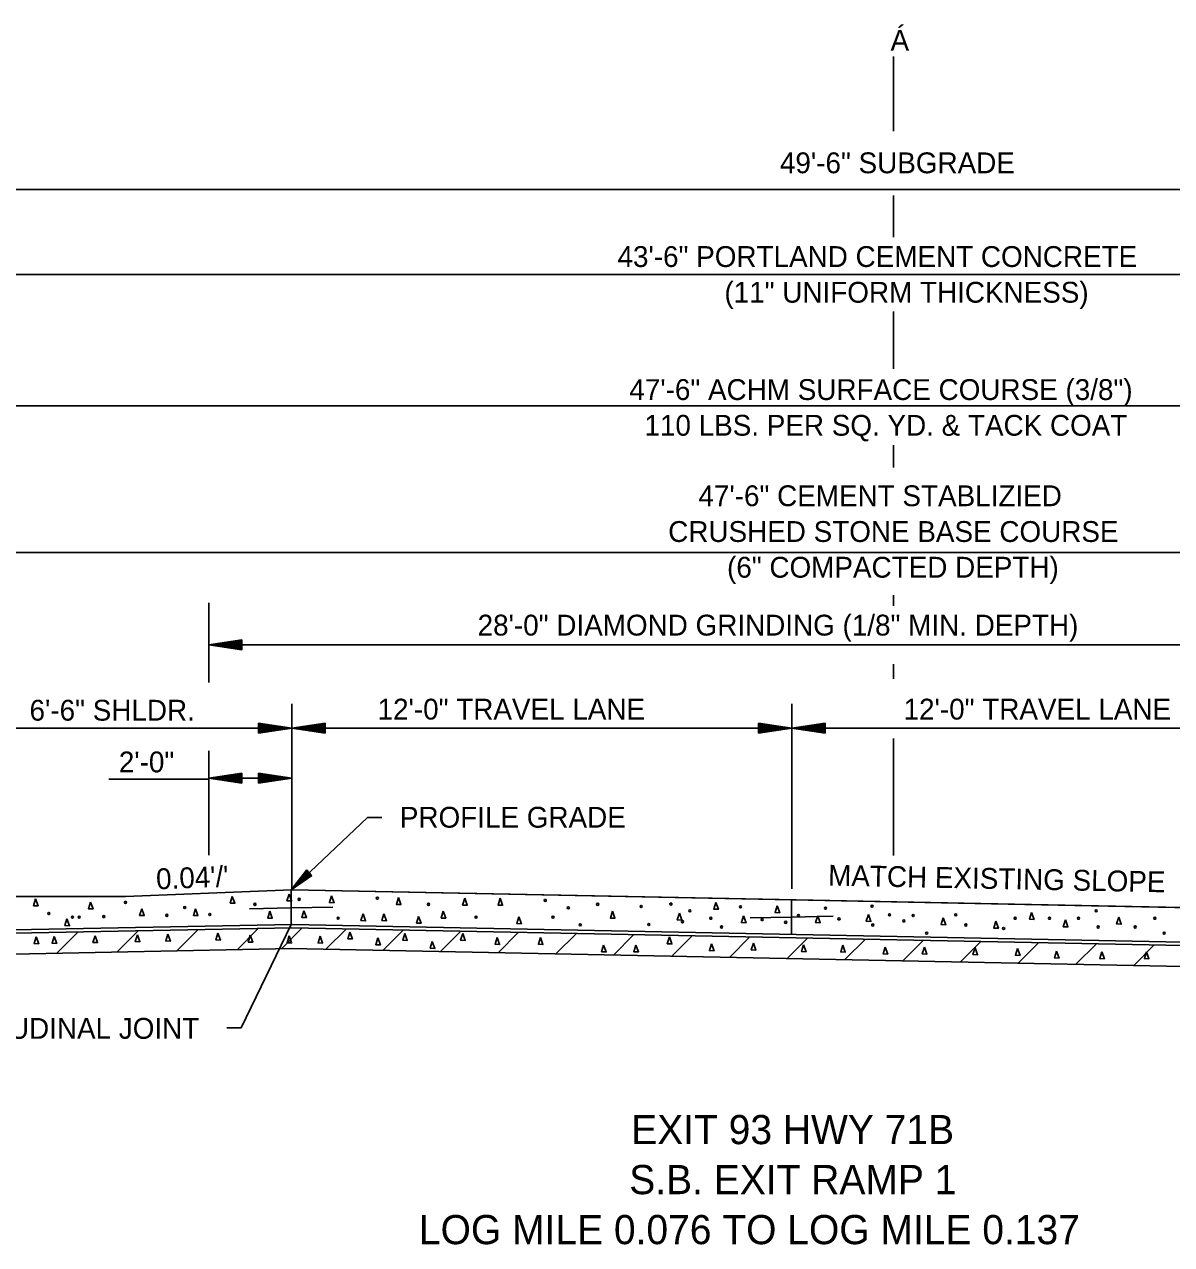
# Model space of a CAD drawing. Extents: x 60325 to 61047, y 53669 to 53767.
# Drawn here: x 60747.15 to 60774.69, y 53684.54 to 53713.82 of the extents above; entities that cross this region are included whole.
import ezdxf

# ---------------------------------------------------------------- set-up
doc = ezdxf.new("R2010")
doc.units = 0
doc.layers.add('R_Border', color=7, linetype='Continuous')
doc.layers.add('R_Border Prem', color=7, linetype='Continuous')

msp = doc.modelspace()

# ---------------------------------------------------------------- linework, layer by layer
at = {"layer": 'R_Border'}
for p, q in [((60751.572, 53698.024), (60751.572, 53699.939)), ((60752.372, 53699.046), (60751.572, 53698.926)), ((60752.372, 53699.026), (60751.706, 53698.926)), ((60752.372, 53698.806), (60752.372, 53699.046)), ((60752.372, 53698.806), (60751.572, 53698.926)), ((60779.572, 53698.926), (60751.572, 53698.926)), ((60752.372, 53698.826), (60751.706, 53698.926)), ((60752.372, 53699.005), (60751.843, 53698.926)), ((60752.372, 53698.846), (60751.843, 53698.926)), ((60752.372, 53698.985), (60751.977, 53698.926)), ((60752.372, 53698.866), (60751.977, 53698.926)), ((60752.372, 53698.965), (60752.112, 53698.926)), ((60752.372, 53698.887), (60752.112, 53698.926)), ((60752.372, 53698.945), (60752.246, 53698.926)), ((60752.372, 53698.907), (60752.246, 53698.926)), ((60753.57, 53693.371), (60753.57, 53697.513)), ((60754.37, 53697.052), (60753.57, 53696.932)), ((60754.37, 53697.032), (60753.704, 53696.932)), ((60754.37, 53697.011), (60753.841, 53696.932)), ((60754.37, 53696.991), (60753.975, 53696.932)), ((60754.37, 53696.971), (60754.11, 53696.932)), ((60754.37, 53696.812), (60754.37, 53697.052)), ((60764.77, 53697.052), (60765.57, 53696.932)), ((60764.77, 53697.052), (60764.77, 53696.812)), ((60764.77, 53697.032), (60765.437, 53696.932)), ((60764.77, 53697.011), (60765.299, 53696.932)), ((60764.77, 53696.991), (60765.166, 53696.932)), ((60764.77, 53696.971), (60765.03, 53696.932)), ((60766.37, 53697.052), (60765.57, 53696.932)), ((60766.37, 53697.032), (60765.704, 53696.932)), ((60766.37, 53697.011), (60765.841, 53696.932)), ((60766.37, 53696.991), (60765.975, 53696.932)), ((60766.37, 53696.971), (60766.11, 53696.932)), ((60766.37, 53696.812), (60766.37, 53697.052)), ((60777.57, 53696.932), (60753.57, 53696.932)), ((60754.37, 53696.812), (60753.57, 53696.932)), ((60754.37, 53696.832), (60753.704, 53696.932)), ((60754.37, 53696.852), (60753.841, 53696.932)), ((60754.37, 53696.872), (60753.975, 53696.932)), ((60754.37, 53696.893), (60754.11, 53696.932)), ((60754.37, 53696.951), (60754.244, 53696.932)), ((60754.37, 53696.913), (60754.244, 53696.932)), ((60764.77, 53696.951), (60764.897, 53696.932)), ((60764.77, 53696.812), (60765.57, 53696.932)), ((60764.77, 53696.893), (60765.03, 53696.932)), ((60764.77, 53696.852), (60765.299, 53696.932)), ((60764.77, 53696.832), (60765.437, 53696.932)), ((60764.77, 53696.872), (60765.166, 53696.932)), ((60764.77, 53696.913), (60764.897, 53696.932)), ((60766.37, 53696.812), (60765.57, 53696.932)), ((60766.37, 53696.832), (60765.704, 53696.932)), ((60766.37, 53696.852), (60765.841, 53696.932)), ((60766.37, 53696.872), (60765.975, 53696.932)), ((60766.37, 53696.893), (60766.11, 53696.932)), ((60766.37, 53696.951), (60766.244, 53696.932)), ((60766.37, 53696.913), (60766.244, 53696.932)), ((60751.572, 53693.881), (60751.572, 53696.382)), ((60752.372, 53695.847), (60751.572, 53695.727)), ((60752.372, 53695.827), (60751.706, 53695.727)), ((60752.372, 53695.806), (60751.843, 53695.727)), ((60752.372, 53695.847), (60752.372, 53695.607)), ((60752.772, 53695.847), (60753.572, 53695.727)), ((60752.772, 53695.847), (60752.772, 53695.607)), ((60752.772, 53695.827), (60753.439, 53695.727)), ((60752.772, 53695.806), (60753.301, 53695.727)), ((60751.572, 53695.707), (60749.178, 53695.707)), ((60753.572, 53695.727), (60751.572, 53695.727)), ((60752.372, 53695.607), (60751.572, 53695.727)), ((60752.372, 53695.627), (60751.706, 53695.727)), ((60752.372, 53695.647), (60751.843, 53695.727)), ((60752.372, 53695.786), (60751.977, 53695.727)), ((60752.372, 53695.667), (60751.977, 53695.727)), ((60752.372, 53695.765), (60752.112, 53695.727)), ((60752.372, 53695.687), (60752.112, 53695.727)), ((60752.372, 53695.745), (60752.246, 53695.727)), ((60752.372, 53695.708), (60752.246, 53695.727)), ((60752.772, 53695.786), (60753.168, 53695.727)), ((60752.772, 53695.765), (60753.032, 53695.727)), ((60752.772, 53695.745), (60752.899, 53695.727)), ((60752.772, 53695.607), (60753.572, 53695.727)), ((60752.772, 53695.687), (60753.032, 53695.727)), ((60752.772, 53695.647), (60753.301, 53695.727)), ((60752.772, 53695.627), (60753.439, 53695.727)), ((60752.772, 53695.667), (60753.168, 53695.727)), ((60752.772, 53695.708), (60752.899, 53695.727)), ((60753.554, 53693.033), (60753.554, 53692.2)), ((60753.554, 53692.617), (60752.555, 53692.597)), ((60754.554, 53692.637), (60753.554, 53692.617)), ((60765.568, 53692.812), (60765.568, 53691.979)), ((60765.568, 53692.395), (60764.568, 53692.375)), ((60766.568, 53692.415), (60765.568, 53692.395)), ((60752.353, 53689.741), (60753.554, 53692.221)), ((60752.007, 53689.741), (60752.353, 53689.741))]:
    msp.add_line(p, q, dxfattribs=at)
msp.add_lwpolyline([(60751.571, 53692.97), (60753.572, 53693.051), (60777.57, 53692.571), (60779.572, 53692.49)], dxfattribs=at)
at = {"layer": 'R_Border Prem'}
for p, q in [((60768.01, 53711.254), (60768.01, 53713.048)), ((60791.429, 53709.854), (60741.764, 53709.854)), ((60768.01, 53708.708), (60768.01, 53709.714)), ((60788.618, 53707.813), (60744.576, 53707.813)), ((60768.01, 53705.552), (60768.01, 53706.927)), ((60790.388, 53704.661), (60742.805, 53704.661)), ((60768.01, 53703.182), (60768.01, 53703.717)), ((60790.388, 53701.145), (60742.805, 53701.145)), ((60768.01, 53699.869), (60768.01, 53700.124)), ((60768.01, 53698.116), (60768.01, 53698.464)), ((60753.57, 53693.071), (60753.57, 53697.513)), ((60765.57, 53693.071), (60765.57, 53697.513)), ((60752.77, 53697.052), (60753.57, 53696.932)), ((60752.77, 53697.052), (60752.77, 53696.812)), ((60752.77, 53697.032), (60753.437, 53696.932)), ((60752.77, 53697.011), (60753.299, 53696.932)), ((60752.77, 53696.991), (60753.166, 53696.932)), ((60752.77, 53696.971), (60753.03, 53696.932)), ((60745.57, 53696.932), (60753.57, 53696.932)), ((60752.77, 53696.951), (60752.897, 53696.932)), ((60752.77, 53696.812), (60753.57, 53696.932)), ((60752.77, 53696.893), (60753.03, 53696.932)), ((60752.77, 53696.852), (60753.299, 53696.932)), ((60752.77, 53696.832), (60753.437, 53696.932)), ((60752.77, 53696.872), (60753.166, 53696.932)), ((60752.77, 53696.913), (60752.897, 53696.932)), ((60768.01, 53693.874), (60768.01, 53696.684)), ((60753.925, 53693.529), (60753.552, 53693.051)), ((60753.936, 53693.518), (60753.624, 53693.12)), ((60753.946, 53693.507), (60753.699, 53693.191)), ((60753.957, 53693.496), (60753.772, 53693.259)), ((60753.967, 53693.485), (60753.846, 53693.329)), ((60753.978, 53693.474), (60753.918, 53693.398)), ((60753.997, 53693.453), (60753.918, 53693.398)), ((60754.049, 53693.398), (60753.925, 53693.529)), ((60754.049, 53693.398), (60753.552, 53693.051)), ((60754.039, 53693.409), (60753.624, 53693.12)), ((60754.028, 53693.42), (60753.699, 53693.191)), ((60754.018, 53693.431), (60753.772, 53693.259)), ((60754.007, 53693.442), (60753.846, 53693.329)), ((60749.572, 53692.891), (60745.572, 53692.891)), ((60753.57, 53693.05), (60749.572, 53692.891)), ((60753.57, 53693.051), (60777.57, 53692.571)), ((60753.572, 53692.141), (60742.639, 53691.922)), ((60753.572, 53692.221), (60742.805, 53692.005)), ((60747.923, 53691.528), (60748.434, 53692.038)), ((60749.366, 53691.556), (60749.877, 53692.067)), ((60750.81, 53691.585), (60751.32, 53692.095)), ((60752.253, 53691.614), (60752.763, 53692.124)), ((60753.33, 53691.645), (60753.82, 53692.136)), ((60753.572, 53692.141), (60779.57, 53691.621)), ((60753.574, 53692.22), (60779.57, 53691.701)), ((60754.386, 53691.624), (60754.877, 53692.114)), ((60755.756, 53691.597), (60756.246, 53692.087)), ((60757.139, 53691.569), (60757.629, 53692.059)), ((60758.524, 53691.541), (60759.014, 53692.032)), ((60759.909, 53691.514), (60760.399, 53692.004)), ((60761.291, 53691.486), (60761.781, 53691.976)), ((60762.689, 53691.458), (60763.179, 53691.948)), ((60764.075, 53691.43), (60764.566, 53691.921)), ((60765.462, 53691.403), (60765.952, 53691.893)), ((60766.848, 53691.375), (60767.339, 53691.865)), ((60768.235, 53691.347), (60768.725, 53691.837)), ((60769.621, 53691.32), (60770.111, 53691.81)), ((60771.008, 53691.292), (60771.498, 53691.782)), ((60772.394, 53691.264), (60772.884, 53691.754)), ((60773.781, 53691.236), (60774.271, 53691.727)), ((60753.572, 53691.641), (60741.597, 53691.401)), ((60753.531, 53691.641), (60779.488, 53691.122))]:
    msp.add_line(p, q, dxfattribs=at)
for points in [[(60755.727, 53694.784), (60755.382, 53694.784), (60753.552, 53693.051)], [(60752.139, 53692.893), (60752.2, 53692.727), (60752.09, 53692.732), (60752.139, 53692.893)], [(60753.501, 53692.949), (60753.561, 53692.783), (60753.451, 53692.787), (60753.501, 53692.949)], [(60754.521, 53692.906), (60754.581, 53692.74), (60754.471, 53692.745), (60754.521, 53692.906)], [(60756.128, 53692.864), (60756.188, 53692.698), (60756.078, 53692.702), (60756.128, 53692.864)], [(60747.418, 53692.831), (60747.478, 53692.665), (60747.368, 53692.67), (60747.418, 53692.831)], [(60748.736, 53692.757), (60748.796, 53692.591), (60748.686, 53692.595), (60748.736, 53692.757)], [(60749.964, 53692.598), (60750.024, 53692.432), (60749.914, 53692.437), (60749.964, 53692.598)], [(60751.253, 53692.598), (60751.314, 53692.432), (60751.204, 53692.437), (60751.253, 53692.598)], [(60757.718, 53692.847), (60757.778, 53692.681), (60757.668, 53692.685), (60757.718, 53692.847)], [(60758.568, 53692.847), (60758.628, 53692.681), (60758.518, 53692.685), (60758.568, 53692.847)], [(60763.747, 53692.749), (60763.808, 53692.583), (60763.698, 53692.587), (60763.747, 53692.749)], [(60765.221, 53692.668), (60765.282, 53692.502), (60765.172, 53692.506), (60765.221, 53692.668)], [(60748.17, 53692.355), (60748.231, 53692.189), (60748.121, 53692.194), (60748.17, 53692.355)], [(60753.038, 53692.536), (60753.099, 53692.37), (60752.989, 53692.374), (60753.038, 53692.536)], [(60753.858, 53692.549), (60753.918, 53692.383), (60753.808, 53692.387), (60753.858, 53692.549)], [(60755.278, 53692.472), (60755.338, 53692.306), (60755.228, 53692.311), (60755.278, 53692.472)], [(60755.779, 53692.472), (60755.84, 53692.306), (60755.73, 53692.311), (60755.779, 53692.472)], [(60756.612, 53692.413), (60756.673, 53692.247), (60756.563, 53692.251), (60756.612, 53692.413)], [(60757.204, 53692.536), (60757.265, 53692.37), (60757.155, 53692.374), (60757.204, 53692.536)], [(60759.018, 53692.404), (60759.079, 53692.238), (60758.969, 53692.243), (60759.018, 53692.404)], [(60761.266, 53692.536), (60761.326, 53692.37), (60761.216, 53692.374), (60761.266, 53692.536)], [(60762.872, 53692.49), (60762.933, 53692.324), (60762.823, 53692.328), (60762.872, 53692.49)], [(60764.411, 53692.425), (60764.472, 53692.259), (60764.362, 53692.263), (60764.411, 53692.425)], [(60766.193, 53692.425), (60766.254, 53692.259), (60766.144, 53692.263), (60766.193, 53692.425)], [(60767.409, 53692.457), (60767.469, 53692.291), (60767.359, 53692.296), (60767.409, 53692.457)], [(60769.207, 53692.376), (60769.267, 53692.21), (60769.157, 53692.215), (60769.207, 53692.376)], [(60770.47, 53692.295), (60770.531, 53692.129), (60770.421, 53692.134), (60770.47, 53692.295)], [(60771.329, 53692.506), (60771.39, 53692.34), (60771.28, 53692.344), (60771.329, 53692.506)], [(60772.139, 53692.328), (60772.2, 53692.162), (60772.09, 53692.166), (60772.139, 53692.328)], [(60773.419, 53692.392), (60773.479, 53692.226), (60773.369, 53692.231), (60773.419, 53692.392)], [(60750.592, 53691.984), (60750.653, 53691.818), (60750.543, 53691.823), (60750.592, 53691.984)], [(60751.794, 53692.008), (60751.855, 53691.842), (60751.745, 53691.847), (60751.794, 53692.008)], [(60754.964, 53692.037), (60755.024, 53691.871), (60754.914, 53691.875), (60754.964, 53692.037)], [(60756.28, 53692.003), (60756.341, 53691.837), (60756.231, 53691.841), (60756.28, 53692.003)], [(60757.67, 53692.003), (60757.73, 53691.837), (60757.62, 53691.841), (60757.67, 53692.003)], [(60747.431, 53691.921), (60747.491, 53691.755), (60747.381, 53691.759), (60747.431, 53691.921)], [(60747.863, 53691.93), (60747.924, 53691.764), (60747.814, 53691.768), (60747.863, 53691.93)], [(60748.844, 53691.949), (60748.904, 53691.783), (60748.794, 53691.788), (60748.844, 53691.949)], [(60749.86, 53691.969), (60749.921, 53691.803), (60749.811, 53691.808), (60749.86, 53691.969)], [(60752.572, 53691.96), (60752.632, 53691.794), (60752.522, 53691.798), (60752.572, 53691.96)], [(60753.503, 53691.943), (60753.564, 53691.777), (60753.454, 53691.782), (60753.503, 53691.943)], [(60754.247, 53691.94), (60754.307, 53691.774), (60754.197, 53691.778), (60754.247, 53691.94)], [(60755.634, 53691.896), (60755.695, 53691.73), (60755.585, 53691.734), (60755.634, 53691.896)], [(60756.941, 53691.808), (60757.002, 53691.642), (60756.892, 53691.647), (60756.941, 53691.808)], [(60758.495, 53691.904), (60758.556, 53691.738), (60758.446, 53691.743), (60758.495, 53691.904)], [(60759.537, 53691.904), (60759.597, 53691.738), (60759.487, 53691.743), (60759.537, 53691.904)], [(60761.054, 53691.726), (60761.115, 53691.56), (60761.005, 53691.564), (60761.054, 53691.726)], [(60761.828, 53691.726), (60761.889, 53691.56), (60761.779, 53691.564), (60761.828, 53691.726)], [(60762.632, 53691.919), (60762.692, 53691.753), (60762.582, 53691.758), (60762.632, 53691.919)], [(60763.643, 53691.755), (60763.704, 53691.589), (60763.594, 53691.594), (60763.643, 53691.755)], [(60764.648, 53691.771), (60764.708, 53691.605), (60764.598, 53691.61), (60764.648, 53691.771)], [(60765.855, 53691.731), (60765.915, 53691.565), (60765.805, 53691.569), (60765.855, 53691.731)], [(60766.794, 53691.723), (60766.855, 53691.557), (60766.745, 53691.561), (60766.794, 53691.723)], [(60767.815, 53691.674), (60767.875, 53691.508), (60767.765, 53691.513), (60767.815, 53691.674)], [(60768.755, 53691.674), (60768.815, 53691.508), (60768.705, 53691.513), (60768.755, 53691.674)], [(60769.97, 53691.658), (60770.03, 53691.492), (60769.92, 53691.497), (60769.97, 53691.658)], [(60770.99, 53691.642), (60771.051, 53691.476), (60770.941, 53691.48), (60770.99, 53691.642)], [(60771.93, 53691.577), (60771.99, 53691.411), (60771.88, 53691.416), (60771.93, 53691.577)], [(60773.015, 53691.561), (60773.076, 53691.395), (60772.966, 53691.399), (60773.015, 53691.561)], [(60774.085, 53691.561), (60774.145, 53691.395), (60774.035, 53691.399), (60774.085, 53691.561)]]:
    msp.add_lwpolyline(points, dxfattribs=at)
for centre in [(60755.622, 53692.849), (60749.574, 53692.749), (60750.997, 53692.625), (60752.683, 53692.703), (60753.743, 53692.823), (60756.849, 53692.703), (60759.653, 53692.797), (60760.207, 53692.617), (60760.911, 53692.703), (60761.956, 53692.651), (60762.67, 53692.709), (60763.124, 53692.547), (60764.339, 53692.644), (60766.38, 53692.611), (60767.498, 53692.66), (60772.877, 53692.547), (60747.734, 53692.482), (60748.301, 53692.393), (60748.462, 53692.396), (60749.052, 53692.408), (60750.566, 53692.439), (60751.602, 53692.459), (60754.679, 53692.372), (60757.991, 53692.393), (60759.838, 53692.393), (60762.946, 53692.287), (60763.626, 53692.368), (60764.858, 53692.336), (60765.425, 53692.271), (60765.732, 53692.433), (60766.704, 53692.352), (60767.919, 53692.449), (60768.26, 53692.304), (60768.486, 53692.433), (60769.507, 53692.449), (60770.933, 53692.368), (60771.759, 53692.368), (60772.456, 53692.368), (60774.286, 53692.368), (60760.493, 53692.213), (60762.14, 53692.218), (60763.886, 53692.158), (60767.514, 53692.206), (60768.81, 53692.012), (60769.75, 53692.206), (60770.657, 53692.125), (60772.925, 53692.158), (60773.816, 53692.158), (60774.513, 53692.012)]:
    msp.add_circle(centre, 0.025, dxfattribs=at)

# ---------------------------------------------------------------- texts
at = {"layer": 'R_Border'}
for s, height, p in [('28\'-0" DIAMOND GRINDING (1/8" MIN. DEPTH)', 0.5, (60758.029, 53699.152)), ('12\'-0" TRAVEL LANE', 0.5, (60755.627, 53697.136)), ('12\'-0" TRAVEL LANE', 0.5, (60768.255, 53697.136)), ('2\'-0"', 0.5, (60749.415, 53695.869)), ('LONGITUDINAL JOINT', 0.5, (60744.288, 53689.476)), ('EXIT 93 HWY 71B', 0.7, (60761.716, 53686.948)), ('S.B. EXIT RAMP 1', 0.7, (60761.669, 53685.748)), ('LOG MILE 0.076 TO LOG MILE 0.137', 0.7, (60756.619, 53684.548))]:
    msp.add_text(s, height=height, dxfattribs=at).set_placement(p)
msp.add_text('MATCH EXISTING SLOPE', height=0.5, rotation=358.8542, dxfattribs=at).set_placement((60766.44, 53693.152))
at = {"layer": 'R_Border Prem'}
for s, p in [('Á', (60767.942, 53713.186)), ('49\'-6" SUBGRADE', (60765.286, 53710.245)), ('43\'-6" PORTLAND CEMENT CONCRETE', (60761.387, 53707.996)), ('(11" UNIFORM THICKNESS)', (60763.954, 53707.139)), ('47\'-6" ACHM SURFACE COURSE (3/8")', (60761.671, 53704.804)), ('110 LBS. PER SQ. YD. & TACK COAT', (60762.034, 53703.947)), ('47\'-6" CEMENT STABLIZIED', (60763.33, 53702.256)), ('CRUSHED STONE BASE COURSE', (60762.604, 53701.398)), ('(6" COMPACTED DEPTH)', (60764.017, 53700.541)), ('6\'-6" SHLDR.', (60747.271, 53697.11)), ('PROFILE GRADE', (60756.162, 53694.542))]:
    msp.add_text(s, height=0.5, dxfattribs=at).set_placement(p)
msp.add_text("0.04'/'", height=0.5, rotation=2.2906, dxfattribs=at).set_placement((60750.319, 53693.06))

doc.saveas('drawing.dxf')
